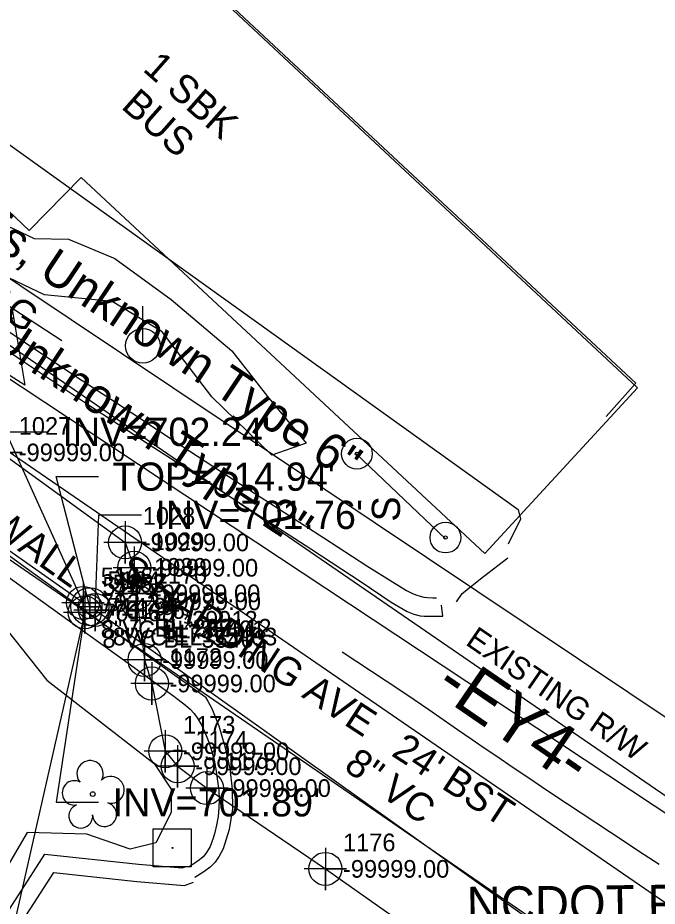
# Model space of a CAD drawing. Extents: x 1516784 to 1522736, y 634838 to 639369.
# Drawn here: x 1520280.1 to 1520370.7, y 637545.3 to 637671.2 of the extents above; entities that cross this region are included whole.
import ezdxf

# ---------------------------------------------------------------- set-up
doc = ezdxf.new("R2010")
doc.units = 0
for name, color, linetype in [('COGO Default Point Elevation', 7, 'Continuous'), ('COGO Default Point Number', 7, 'Continuous'), ('Exist Building', 7, 'Continuous'), ('Exist Building Leader', 7, 'Continuous'), ('Exist Building Metal Canopy', 7, 'Continuous'), ('Exist Building Text', 7, 'Continuous'), ('Exist Environmental Wetland Boundary Cogo Elevation', 7, 'Continuous'), ('Exist Environmental Wetland Boundary Cogo Number', 7, 'Continuous'), ('Exist Environmental Wetland Boundary Cogo Point CELL', 7, 'Continuous'), ('Exist Environmental Wetland Boundary Text', 7, 'Continuous'), ('Exist Horizontal Alignment Direction Label', 7, 'Continuous'), ('Exist Other Culture Sign CELL', 7, 'Continuous'), ('Exist Other Culture Sign Text', 7, 'Continuous'), ('Exist Right of Way Line', 7, 'Continuous'), ('Exist Right of Way Line Text', 7, 'Continuous'), ('Exist Roads Curbs Text', 7, 'Continuous'), ('Exist Roads EOP Text', 7, 'Continuous'), ('Exist Utilities Other Pole With Base CELL', 7, 'Continuous'), ('Exist Utilities Power Pole CELL', 7, 'Continuous'), ('Exist Utilities Power UG Cable SUE LOS B Text', 7, 'Continuous'), ('Exist Utilities Sanitary Sewer Manhole CELL', 7, 'Continuous'), ('Exist Utilities Sanitary Sewer Manhole Cogo Elevation', 7, 'Continuous'), ('Exist Utilities Sanitary Sewer Manhole Cogo Number', 7, 'Continuous'), ('Exist Utilities Sanitary Sewer Manhole Leader', 7, 'Continuous'), ('Exist Utilities Sanitary Sewer Manhole Text', 7, 'Continuous'), ('Exist Utilities Sanitary Sewer UG Line', 7, 'Continuous'), ('Exist Utilities Sanitary Sewer UG Line Cogo Comment', 7, 'Continuous'), ('Exist Utilities Sanitary Sewer UG Line Cogo Elevation', 7, 'Continuous'), ('Exist Utilities Sanitary Sewer UG Line Cogo Number', 7, 'Continuous'), ('Exist Utilities Sanitary Sewer UG Line Cogo Point CELL', 7, 'Continuous'), ('Exist Utilities Sanitary Sewer UG Line Invert Elevation', 7, 'Continuous'), ('Exist Utilities Sanitary Sewer UG Line Leader', 7, 'Continuous'), ('Exist Utilities Sanitary Sewer UG Line Text', 7, 'Continuous'), ('Exist Utilities Water UG Line SUE LOS B', 7, 'Continuous'), ('Exist Utilities Water UG Line SUE LOS B Cogo Comment', 7, 'Continuous'), ('Exist Utilities Water UG Line SUE LOS B Cogo Elevation', 7, 'Continuous'), ('Exist Utilities Water UG Line SUE LOS B Cogo Number', 7, 'Continuous'), ('Exist Utilities Water UG Line SUE LOS B Cogo Point CELL', 7, 'Continuous'), ('Exist Utilities Water UG Line SUE LOS C', 7, 'Continuous'), ('Exist Utilities Water UG Line SUE LOS C Text', 7, 'Continuous'), ('Exist Vegetation Hedge Row', 7, 'Continuous'), ('Exist Vegetation Tree CELL', 7, 'Continuous'), ('Scratch_Level_5', 7, 'Continuous')]:
    doc.layers.add(name, color=color, linetype=linetype)

msp = doc.modelspace()

# ---------------------------------------------------------------- linework, layer by layer
at = {"layer": 'COGO Default Point Elevation'}
msp.add_lwpolyline([(1520326.03, 637581.36), (1520328.11, 637579.98), (1520330.18, 637578.6), (1520332.26, 637577.23), (1520334.33, 637575.85), (1520336.26, 637574.58), (1520338.3, 637573.17), (1520340.35, 637571.75), (1520342.4, 637570.34), (1520344.45, 637568.93), (1520346.02, 637567.85), (1520348.08, 637566.46), (1520350.15, 637565.06), (1520352.21, 637563.67), (1520354.27, 637562.27), (1520355.73, 637561.28), (1520357.81, 637559.91), (1520359.9, 637558.53), (1520361.98, 637557.16), (1520364.06, 637555.79), (1520366.14, 637554.42), (1520366.77, 637554), (1520368.85, 637552.63), (1520370.94, 637551.26)], dxfattribs=at)
at = {"layer": 'COGO Default Point Number'}
for points in [[(1520275.92, 637625.81), (1520280.75, 637622.57), (1520285.42, 637619.45), (1520289.94, 637616.45), (1520294.32, 637613.58), (1520298.69, 637610.73), (1520303.2, 637607.81), (1520307.8, 637604.84), (1520312.46, 637601.84), (1520317.09, 637598.86), (1520321.62, 637595.94), (1520328.86, 637591.16), (1520332.98, 637588.38), (1520335.26, 637587.07), (1520336.19, 637586.7), (1520337.1, 637586.45), (1520337.65, 637586.38), (1520340.3, 637586.39), (1520340.12, 637587.97)], [(1520275.54, 637597.33), (1520281.46, 637593.11), (1520287.42, 637588.79), (1520293.24, 637584.58), (1520299.23, 637580.26), (1520304.79, 637576.3), (1520306.59, 637575.01), (1520306.67, 637574.93), (1520307, 637574.38), (1520307.57, 637573.3), (1520308.57, 637570.84), (1520309.44, 637567.95), (1520310.12, 637564.82), (1520310.46, 637561.89), (1520310.5, 637559.11), (1520310.01, 637556.16), (1520309.16, 637553.43), (1520308.63, 637552.38), (1520308.04, 637551.54), (1520307.36, 637550.84), (1520306.45, 637550.16), (1520305.15, 637549.37)]]:
    msp.add_lwpolyline(points, dxfattribs=at)
at = {"layer": 'Exist Building'}
msp.add_line((1520286.32, 637625.42), (1520259.35, 637642.94), dxfattribs=at)
at = {"layer": 'Exist Building Leader'}
msp.add_lwpolyline([(1520279.25, 637630.16), (1520281.08, 637619.11), (1520272.05, 637624.81)], dxfattribs=at)
at = {"layer": 'Exist Building Metal Canopy'}
msp.add_lwpolyline([(1520267.56, 637712.41), (1520367.88, 637618.75), (1520346.25, 637595.26), (1520289.08, 637648.53), (1520281.68, 637641.04), (1520254.16, 637667.17)], close=True, dxfattribs=at)
at = {"layer": 'Exist Environmental Wetland Boundary Cogo Elevation'}
msp.add_lwpolyline([(1520363.45, 637614.7), (1520367.65, 637619.39), (1520281.28, 637700.02)], dxfattribs=at)
at = {"layer": 'Exist Environmental Wetland Boundary Cogo Number'}
for points in [[(1520276.58, 637628.18), (1520282.58, 637624.15), (1520289.21, 637619.78), (1520296.23, 637615.19), (1520303.37, 637610.5), (1520310.97, 637605.54), (1520315.07, 637602.88), (1520323.44, 637597.47), (1520329.55, 637593.55), (1520333.15, 637591.27), (1520335.16, 637590.05), (1520335.91, 637589.66), (1520336.5, 637589.42), (1520337.09, 637589.24), (1520337.61, 637589.1), (1520338.11, 637589.03), (1520338.91, 637589), (1520339.4, 637589)], [(1520275.03, 637594.63), (1520280.94, 637590.34), (1520287.5, 637585.63), (1520294.35, 637580.73), (1520299.32, 637577.16), (1520302.18, 637575.05), (1520303.83, 637573.8), (1520304.52, 637573.22), (1520305.07, 637572.61), (1520305.6, 637571.86), (1520306.14, 637570.9), (1520306.67, 637569.73), (1520307.15, 637568.56), (1520307.55, 637567.37), (1520307.9, 637566), (1520308.18, 637564.45), (1520308.4, 637563.01), (1520308.57, 637561.69), (1520308.63, 637560.44), (1520308.59, 637559.25), (1520308.46, 637558.03), (1520308.24, 637556.8), (1520308.01, 637555.76), (1520307.76, 637554.94), (1520307.53, 637554.3), (1520307.32, 637553.79), (1520307.07, 637553.3), (1520306.75, 637552.8), (1520306.36, 637552.33), (1520305.85, 637551.89), (1520305.02, 637551.32), (1520304.47, 637550.97)], [(1520234.02, 637454.46), (1520234.33, 637459.2), (1520247.91, 637467.24), (1520252.43, 637469.91), (1520253.01, 637470.68), (1520253.22, 637471.48), (1520252.65, 637472.39), (1520251.6, 637472.97), (1520237.79, 637472.27), (1520237.48, 637481.58), (1520254.01, 637506.71), (1520267.89, 637527.96), (1520280.3, 637547.04), (1520283.92, 637552.69), (1520297.21, 637551.26), (1520303.37, 637550.74), (1520303.81, 637550.9)]]:
    msp.add_lwpolyline(points, dxfattribs=at)
at = {"layer": 'Exist Environmental Wetland Boundary Cogo Point CELL'}
for points in [[(1520277.18, 637742.83), (1520268.15, 637716.16), (1520253.1, 637671.65), (1520350.99, 637601.5)], [(1520350.99, 637601.5), (1520351.29, 637600.14), (1520349.54, 637596.58)], [(1520342.25, 637588.44), (1520343.03, 637589.62), (1520346.06, 637592), (1520349.53, 637594.65)], [(1520236.48, 637454.3), (1520236.7, 637457.75), (1520249.16, 637465.12), (1520254.1, 637468.04), (1520255.27, 637469.59), (1520255.86, 637471.88), (1520254.41, 637474.23), (1520252.17, 637475.46), (1520240.16, 637474.85), (1520239.96, 637480.88), (1520256.07, 637505.36), (1520269.95, 637526.62), (1520282.37, 637545.71), (1520285.17, 637550.09), (1520296.97, 637548.81), (1520303.69, 637548.25), (1520304.97, 637548.7)]]:
    msp.add_lwpolyline(points, dxfattribs=at)
at = {"layer": 'Exist Environmental Wetland Boundary Text'}
msp.add_line((1520252.73, 637627.58), (1520443.72, 637496.45), dxfattribs=at)
at = {"layer": 'Exist Other Culture Sign CELL'}
msp.add_line((1520340.69, 637597.35), (1520328.02, 637609.4), dxfattribs=at)
for centre, radius in [((1520328.13, 637609.41), 2.18), ((1520328.13, 637609.41), 0.24), ((1520340.68, 637597.53), 2.18), ((1520340.68, 637597.53), 0.24)]:
    msp.add_circle(centre, radius, dxfattribs=at)
at = {"layer": 'Exist Right of Way Line'}
for p, q in [((1520259.8, 637637.89), (1520393.32, 637546.21)), ((1520245.65, 637617.28), (1520392.38, 637516.53))]:
    msp.add_line(p, q, dxfattribs=at)
at = {"layer": 'Exist Utilities Other Pole With Base CELL'}
msp.add_line((1520301.99, 637553.57), (1520301.99, 637553.57), dxfattribs=at)
msp.add_lwpolyline([(1520299.26, 637556.27), (1520304.66, 637556.27), (1520304.66, 637550.87), (1520299.26, 637550.87), (1520299.26, 637556.27)], dxfattribs=at)
msp.add_circle((1520301.99, 637553.57), 0.0707, dxfattribs=at)
at = {"layer": 'Exist Utilities Power Pole CELL'}
for q in [(1520297.8, 637630.33), (1520297.8, 637624.7)]:
    msp.add_line((1520297.8, 637624.7), q, dxfattribs=at)
msp.add_circle((1520297.8, 637624.7), 2.45, dxfattribs=at)
at = {"layer": 'Exist Utilities Sanitary Sewer Manhole CELL'}
msp.add_lwpolyline([(1520290.3, 637589.45), (1520290.3, 637586.03), (1520290.3, 637587.74), (1520292.02, 637587.74), (1520288.59, 637587.74)], dxfattribs=at)
for radius in [2.69, 1.71]:
    msp.add_circle((1520290.3, 637587.74), radius, dxfattribs=at)
at = {"layer": 'Exist Utilities Sanitary Sewer Manhole Leader'}
msp.add_lwpolyline([(1520290.3, 637587.74), (1520285.52, 637606.16), (1520291.52, 637606.16)], dxfattribs=at)
at = {"layer": 'Exist Utilities Sanitary Sewer UG Line'}
for p, q in [((1520289.34, 637588.28), (1520208.86, 637645.03)), ((1520289.58, 637586.93), (1520252.4, 637422.76)), ((1520402, 637508.25), (1520291.04, 637587.26))]:
    msp.add_line(p, q, dxfattribs=at)
at = {"layer": 'Exist Utilities Sanitary Sewer UG Line Cogo Point CELL'}
for points in [[(1520289.34, 637591.28), (1520289.34, 637585.28), (1520289.34, 637588.28), (1520292.34, 637588.28), (1520286.34, 637588.28)], [(1520291.04, 637590.26), (1520291.04, 637584.26), (1520291.04, 637587.26), (1520294.04, 637587.26), (1520288.04, 637587.26)], [(1520289.58, 637589.93), (1520289.58, 637583.93), (1520289.58, 637586.93), (1520292.58, 637586.93), (1520286.58, 637586.93)]]:
    msp.add_lwpolyline(points, dxfattribs=at)
for centre in [(1520289.34, 637588.28), (1520289.58, 637586.93), (1520291.04, 637587.26)]:
    msp.add_circle(centre, 2.34, dxfattribs=at)
at = {"layer": 'Exist Utilities Sanitary Sewer UG Line Leader'}
for points in [[(1520289.34, 637588.28), (1520278.41, 637612.51), (1520284.41, 637612.51)], [(1520291.04, 637587.26), (1520291.59, 637600.75), (1520297.59, 637600.75)], [(1520289.58, 637586.93), (1520285.52, 637560.03), (1520291.52, 637560.03)]]:
    msp.add_lwpolyline(points, dxfattribs=at)
at = {"layer": 'Exist Utilities Water UG Line SUE LOS B'}
for points in [[(1520056.08, 637762.82), (1520067.75, 637754.4), (1520081.97, 637743.85), (1520118.87, 637719), (1520135.63, 637708.46), (1520148.05, 637700.76), (1520162.05, 637691.7), (1520182.82, 637678.9), (1520181.78, 637676.92), (1520184.32, 637675.25), (1520186.95, 637673.07), (1520202.92, 637661.84), (1520220.49, 637650.2), (1520248.02, 637630.34), (1520260.83, 637621.31), (1520277.72, 637609.59), (1520295.29, 637596.84), (1520296.58, 637593.25), (1520296.88, 637589.63)], [(1520296.98, 637588.5), (1520298.04, 637580.19), (1520299.08, 637576.86), (1520300.98, 637567.26), (1520302.73, 637565.14), (1520306.88, 637562.04), (1520323.66, 637550.6), (1520341.44, 637538.09), (1520363.95, 637522.88), (1520369.43, 637518.69)]]:
    msp.add_lwpolyline(points, dxfattribs=at)
at = {"layer": 'Exist Utilities Water UG Line SUE LOS B Cogo Point CELL'}
for points in [[(1520277.72, 637612.59), (1520277.72, 637606.59), (1520277.72, 637609.59), (1520280.72, 637609.59), (1520274.72, 637609.59)], [(1520295.29, 637599.84), (1520295.29, 637593.84), (1520295.29, 637596.84), (1520298.29, 637596.84), (1520292.29, 637596.84)], [(1520296.58, 637596.25), (1520296.58, 637590.25), (1520296.58, 637593.25), (1520299.58, 637593.25), (1520293.58, 637593.25)], [(1520296.88, 637592.63), (1520296.88, 637586.63), (1520296.88, 637589.63), (1520299.88, 637589.63), (1520293.88, 637589.63)], [(1520296.98, 637591.5), (1520296.98, 637585.5), (1520296.98, 637588.5), (1520299.98, 637588.5), (1520293.98, 637588.5)], [(1520298.04, 637583.19), (1520298.04, 637577.19), (1520298.04, 637580.19), (1520301.04, 637580.19), (1520295.04, 637580.19)], [(1520299.08, 637579.86), (1520299.08, 637573.86), (1520299.08, 637576.86), (1520302.08, 637576.86), (1520296.08, 637576.86)], [(1520300.98, 637570.26), (1520300.98, 637564.26), (1520300.98, 637567.26), (1520303.98, 637567.26), (1520297.98, 637567.26)], [(1520302.73, 637568.14), (1520302.73, 637562.14), (1520302.73, 637565.14), (1520305.73, 637565.14), (1520299.73, 637565.14)], [(1520306.88, 637565.04), (1520306.88, 637559.04), (1520306.88, 637562.04), (1520309.88, 637562.04), (1520303.88, 637562.04)], [(1520323.66, 637553.6), (1520323.66, 637547.6), (1520323.66, 637550.6), (1520326.66, 637550.6), (1520320.66, 637550.6)]]:
    msp.add_lwpolyline(points, dxfattribs=at)
for centre in [(1520295.29, 637596.84), (1520296.58, 637593.25), (1520296.88, 637589.63), (1520296.98, 637588.5), (1520298.04, 637580.19), (1520299.08, 637576.86), (1520300.98, 637567.26), (1520302.73, 637565.14), (1520306.88, 637562.04), (1520323.66, 637550.6)]:
    msp.add_circle(centre, 2.34, dxfattribs=at)
at = {"layer": 'Exist Utilities Water UG Line SUE LOS C'}
msp.add_line((1520215.9, 637661.73), (1520379.84, 637553.22), dxfattribs=at)
msp.add_lwpolyline([(1520230.15, 637666.84), (1520381.06, 637565.94), (1520393.9, 637576.3)], dxfattribs=at)
at = {"layer": 'Exist Vegetation Hedge Row'}
for points in [[(1520275.28, 637643.26), (1520282.42, 637639.9), (1520287.26, 637639.78), (1520293.85, 637637.08), (1520301.8, 637631.26), (1520310.41, 637623.99), (1520315.44, 637617.49), (1520320.96, 637610.91), (1520316.06, 637609.19), (1520307.58, 637617.45), (1520300.54, 637626.66), (1520293.48, 637630.95), (1520283.88, 637631.93), (1520271.94, 637637.58)], [(1520278.38, 637584.64), (1520284.2, 637577.34), (1520299.41, 637565.54), (1520301.82, 637561.91), (1520301.8, 637558.59), (1520299.63, 637554.31), (1520296.01, 637553.41), (1520289.87, 637555.52), (1520281.4, 637555.76), (1520271.22, 637538.38), (1520258.3, 637516.27), (1520243.31, 637493.12), (1520232.7, 637474.89), (1520228.85, 637467.05), (1520227.67, 637462.55), (1520228.57, 637456.92)]]:
    msp.add_lwpolyline(points, dxfattribs=at)
at = {"layer": 'Exist Vegetation Tree CELL'}
msp.add_line((1520290.71, 637561.2), (1520290.71, 637561.2), dxfattribs=at)
msp.add_circle((1520290.71, 637561.2), 0.326, dxfattribs=at)
for centre, radius, start, end in [((1520290.33, 637564.08), 1.86, 330.1651, 219.7134), ((1520288.11, 637561.36), 1.73, 62.6636, 279.3457), ((1520293.26, 637561.79), 1.9, 257.1011, 134.1999), ((1520292.39, 637558.3), 1.7, 181.2822, 74.56), ((1520289.01, 637558.08), 1.69, 111.5671, 6.231)]:
    msp.add_arc(centre, radius, start, end, dxfattribs=at)

# ---------------------------------------------------------------- texts
at = {"layer": 'Exist Building Text'}
for s, rotation, p in [('1 SBK', 318.5528, (1520297.65, 637663.73)), ('BUS', 318.5528, (1520294.58, 637658.44)), ('30"X12" CONC RET WALL', 324.5997, (1520234.91, 637627.78))]:
    msp.add_text(s, height=4, rotation=rotation, dxfattribs=at).set_placement(p)
at = {"layer": 'Exist Horizontal Alignment Direction Label'}
msp.add_text('-EY4-', height=7, rotation=325.5258, dxfattribs=at).set_placement((1520338.84, 637575.73))
at = {"layer": 'Exist Other Culture Sign Text'}
msp.add_text('S', height=4, rotation=88.3731, dxfattribs=at).set_placement((1520334.19, 637599.75))
at = {"layer": 'Exist Right of Way Line Text'}
msp.add_text('EXISTING R/W', height=3.2, rotation=325.5258, dxfattribs=at).set_placement((1520343.37, 637582.45))
at = {"layer": 'Exist Roads Curbs Text'}
msp.add_text('30"C&G', height=4, rotation=326.6122, dxfattribs=at).set_placement((1520265.11, 637637.08))
at = {"layer": 'Exist Roads EOP Text'}
msp.add_text("S HARDING AVE   24' BST", height=4, rotation=326.8787, dxfattribs=at).set_placement((1520294.03, 637592.07))
at = {"layer": 'Exist Utilities Power UG Cable SUE LOS B Text'}
msp.add_text('NCDOT Pole', height=5, rotation=0.6235, dxfattribs=at).set_placement((1520343.71, 637543.05))
at = {"layer": 'Exist Utilities Sanitary Sewer Manhole Cogo Elevation'}
msp.add_text('714.94', height=2.5, dxfattribs=at).set_placement((1520292.8, 637586.49))
at = {"layer": 'Exist Utilities Sanitary Sewer Manhole Cogo Number'}
msp.add_text('5164', height=2.5, dxfattribs=at).set_placement((1520292.8, 637590.24))
at = {"layer": 'Exist Utilities Sanitary Sewer Manhole Text'}
msp.add_text("TOP=714.94'", height=4, dxfattribs=at).set_placement((1520293.52, 637604.16))
at = {"layer": 'Exist Utilities Sanitary Sewer UG Line Cogo Comment'}
for s, p in [('8"VC BL*35401', (1520291.84, 637583.28)), ('8"VC BL*35403', (1520292.08, 637581.93)), ('8"VC EL*35403', (1520293.54, 637582.26))]:
    msp.add_text(s, height=2.5, dxfattribs=at).set_placement(p)
at = {"layer": 'Exist Utilities Sanitary Sewer UG Line Cogo Elevation'}
for s, p in [('702.24', (1520291.84, 637587.03)), ('701.89', (1520292.08, 637585.68)), ('701.76', (1520293.54, 637586.01))]:
    msp.add_text(s, height=2.5, dxfattribs=at).set_placement(p)
at = {"layer": 'Exist Utilities Sanitary Sewer UG Line Cogo Number'}
for s, p in [('5166', (1520291.84, 637590.78)), ('5165', (1520292.08, 637589.43)), ('5163', (1520293.54, 637589.76))]:
    msp.add_text(s, height=2.5, dxfattribs=at).set_placement(p)
at = {"layer": 'Exist Utilities Sanitary Sewer UG Line Invert Elevation'}
for s, p in [("INV=702.24'", (1520286.41, 637610.51)), ("INV=701.76'", (1520299.59, 637598.75)), ("INV=701.89'", (1520293.52, 637558.03))]:
    msp.add_text(s, height=4, dxfattribs=at).set_placement(p)
at = {"layer": 'Exist Utilities Sanitary Sewer UG Line Text'}
msp.add_text('8" VC', height=4, rotation=324.5461, dxfattribs=at).set_placement((1520326.11, 637564.74))
at = {"layer": 'Exist Utilities Water UG Line SUE LOS B Cogo Comment'}
for s, p in [('EL*29912', (1520299.38, 637584.63)), ('BL*299112', (1520299.48, 637583.5))]:
    msp.add_text(s, height=2.5, dxfattribs=at).set_placement(p)
at = {"layer": 'Exist Utilities Water UG Line SUE LOS B Cogo Elevation'}
for p in [(1520280.22, 637608.34), (1520297.79, 637595.59), (1520299.08, 637592), (1520299.38, 637588.38), (1520299.48, 637587.25), (1520300.54, 637578.94), (1520301.58, 637575.61), (1520303.48, 637566.01), (1520305.23, 637563.89), (1520309.38, 637560.79), (1520326.16, 637549.35)]:
    msp.add_text('-99999.00', height=2.5, dxfattribs=at).set_placement(p)
at = {"layer": 'Exist Utilities Water UG Line SUE LOS B Cogo Number'}
for s, p in [('1027', (1520280.22, 637612.09)), ('1028', (1520297.79, 637599.34)), ('1029', (1520299.08, 637595.75)), ('1030', (1520299.38, 637592.13)), ('1170', (1520299.48, 637591)), ('1171', (1520300.54, 637582.69)), ('1172', (1520301.58, 637579.36)), ('1173', (1520303.48, 637569.76)), ('1174', (1520305.23, 637567.64)), ('1175', (1520309.38, 637564.54)), ('1176', (1520326.16, 637553.1))]:
    msp.add_text(s, height=2.5, dxfattribs=at).set_placement(p)
at = {"layer": 'Exist Utilities Water UG Line SUE LOS C Text'}
for s, rotation, p in [('City of Kannapolis, Unknown Type 6"', 326.2325, (1520234.96, 637666.63)), ('City of Kannapolis, Unknown Type 2"', 326.4991, (1520227.74, 637656.89))]:
    msp.add_text(s, height=5, rotation=rotation, dxfattribs=at).set_placement(p)
at = {"layer": 'Scratch_Level_5'}
msp.add_text('COLUMN LOCATION', height=500, rotation=335.0373, dxfattribs=at).set_placement((1516680.97, 637558.94))

doc.saveas('drawing.dxf')
